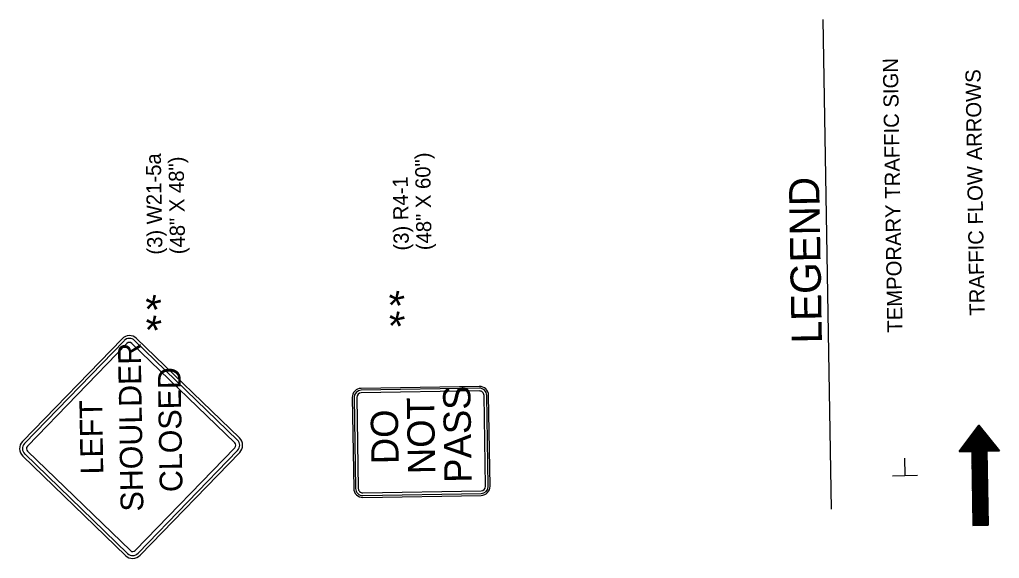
# Model space of a CAD drawing. Extents: x 1676063 to 1678026, y 228339 to 229904.
# Drawn here: x 1677424.3 to 1677812.2, y 228377.9 to 228591.3 of the extents above; entities that cross this region are included whole.
import ezdxf

# ---------------------------------------------------------------- set-up
doc = ezdxf.new("R2010")
doc.units = 0
for name, color, linetype in [('P_TC_Signs_Permanent', 7, 'Continuous'), ('P_TC_Signs_Temporary', 7, 'Continuous'), ('R_Annotation', 7, 'Continuous'), ('R_Draft', 7, 'Continuous'), ('R_MOT', 7, 'Continuous')]:
    doc.layers.add(name, color=color, linetype=linetype)

msp = doc.modelspace()

# ---------------------------------------------------------------- linework, layer by layer
at = {"layer": 'P_TC_Signs_Permanent'}
for p, q in [((1677606.28, 228446), (1677559.49, 228445.22)), ((1677606.29, 228445.28), (1677559.5, 228444.5)), ((1677606.31, 228444.2), (1677559.52, 228443.42)), ((1677555.95, 228441.56), (1677556.54, 228405.57)), ((1677556.67, 228441.58), (1677557.26, 228405.58)), ((1677557.75, 228441.59), (1677558.34, 228405.6)), ((1677608.74, 228406.43), (1677608.14, 228442.43)), ((1677609.82, 228406.45), (1677609.22, 228442.45)), ((1677610.54, 228406.46), (1677609.94, 228442.46)), ((1677560.17, 228403.83), (1677606.97, 228404.6)), ((1677560.19, 228402.75), (1677606.98, 228403.52)), ((1677560.2, 228402.03), (1677607, 228402.81))]:
    msp.add_line(p, q, dxfattribs=at)
for centre, radius, start, end in [((1677559.54, 228441.62), 3.6, 90.9497, 180.9497), ((1677559.54, 228441.62), 2.88, 90.9497, 180.9497), ((1677559.54, 228441.62), 1.8, 90.9497, 180.9497), ((1677606.34, 228442.4), 3.6, 0.9497, 90.9497), ((1677606.34, 228442.4), 2.88, 0.9497, 90.9497), ((1677606.34, 228442.4), 1.8, 0.9497, 90.9497), ((1677560.14, 228405.63), 3.6, 180.9497, 270.9497), ((1677560.14, 228405.63), 2.88, 180.9497, 270.9497), ((1677560.14, 228405.63), 1.8, 180.9497, 270.9497), ((1677606.94, 228406.4), 1.8, 270.9497, 0.9497), ((1677606.94, 228406.4), 2.88, 270.9497, 0.9497), ((1677606.94, 228406.4), 3.6, 270.9497, 0.9497)]:
    msp.add_arc(centre, radius, start, end, dxfattribs=at)
at = {"layer": 'P_TC_Signs_Temporary'}
for p, q in [((1677425.4, 228424.14), (1677464.82, 228464.89)), ((1677426.21, 228423.36), (1677465.63, 228464.11)), ((1677427.34, 228422.26), (1677466.76, 228463.01)), ((1677468.67, 228463.05), (1677509.42, 228423.62)), ((1677469.77, 228464.18), (1677510.52, 228424.76)), ((1677470.55, 228464.99), (1677511.3, 228425.56)), ((1677468.12, 228380.93), (1677427.37, 228420.35)), ((1677509.46, 228421.71), (1677470.03, 228380.96)), ((1677510.59, 228420.62), (1677471.17, 228379.87)), ((1677511.4, 228419.84), (1677471.97, 228379.09)), ((1677466.25, 228378.99), (1677425.49, 228418.41)), ((1677467.03, 228379.8), (1677426.28, 228419.22))]:
    msp.add_line(p, q, dxfattribs=at)
for centre, radius, start, end in [((1677467.73, 228462.08), 4.05, 45.9497, 135.9497), ((1677467.73, 228462.08), 2.93, 45.9497, 135.9497), ((1677467.73, 228462.08), 1.35, 45.9497, 135.9497), ((1677428.31, 228421.32), 4.05, 135.9497, 225.9497), ((1677428.31, 228421.32), 2.93, 135.9497, 225.9497), ((1677508.49, 228422.65), 1.35, 315.9497, 45.9497), ((1677508.49, 228422.65), 2.93, 315.9497, 45.9497), ((1677508.49, 228422.65), 4.05, 315.9497, 45.9497), ((1677428.31, 228421.32), 1.35, 135.9497, 225.9497), ((1677469.06, 228381.9), 1.35, 225.9497, 315.9497), ((1677469.06, 228381.9), 4.05, 225.9497, 315.9497), ((1677469.06, 228381.9), 2.92, 225.9497, 315.9497)]:
    msp.add_arc(centre, radius, start, end, dxfattribs=at)
at = {"layer": 'R_Annotation'}
msp.add_line((1677745.76, 228397.41), (1677742.41, 228591.3), dxfattribs=at)
at = {"layer": 'R_Draft'}
for p, q in [((1677796.23, 228420.15), (1677804.04, 228430.64)), ((1677804.04, 228430.64), (1677812.19, 228420.41)), ((1677796.23, 228420.15), (1677801.22, 228420.23)), ((1677801.22, 228420.23), (1677801.7, 228390.89)), ((1677807.2, 228420.33), (1677812.19, 228420.41)), ((1677807.2, 228420.33), (1677807.69, 228390.99)), ((1677774.83, 228410.83), (1677774.71, 228417.59)), ((1677769.9, 228410.61), (1677779.8, 228410.77)), ((1677801.7, 228390.89), (1677807.69, 228390.99))]:
    msp.add_line(p, q, dxfattribs=at)
at = {"layer": 'R_MOT'}
for p, q in [((1677808.27, 228420.35), (1677801.36, 228427.03)), ((1677808.41, 228420.35), (1677801.42, 228427.12)), ((1677808.55, 228420.35), (1677801.48, 228427.2)), ((1677808.69, 228420.35), (1677801.54, 228427.28)), ((1677808.83, 228420.36), (1677801.6, 228427.36)), ((1677808.98, 228420.36), (1677801.66, 228427.44)), ((1677809.12, 228420.36), (1677801.72, 228427.52)), ((1677809.26, 228420.36), (1677801.78, 228427.6)), ((1677809.4, 228420.37), (1677801.84, 228427.68)), ((1677809.54, 228420.37), (1677801.9, 228427.76)), ((1677809.68, 228420.37), (1677801.96, 228427.84)), ((1677809.82, 228420.37), (1677802.02, 228427.92)), ((1677809.97, 228420.37), (1677802.08, 228428.01)), ((1677810.11, 228420.38), (1677802.14, 228428.09)), ((1677810.25, 228420.38), (1677802.2, 228428.17)), ((1677810.39, 228420.38), (1677802.26, 228428.25)), ((1677810.53, 228420.38), (1677802.32, 228428.33)), ((1677810.67, 228420.39), (1677802.38, 228428.41)), ((1677810.81, 228420.39), (1677802.44, 228428.49)), ((1677810.96, 228420.39), (1677802.5, 228428.57)), ((1677811.1, 228420.39), (1677802.56, 228428.65)), ((1677811.24, 228420.4), (1677802.62, 228428.73)), ((1677811.38, 228420.4), (1677802.68, 228428.81)), ((1677811.52, 228420.4), (1677802.74, 228428.89)), ((1677811.66, 228420.4), (1677802.8, 228428.98)), ((1677811.8, 228420.41), (1677802.86, 228429.06)), ((1677811.95, 228420.41), (1677802.92, 228429.14)), ((1677812.09, 228420.41), (1677802.98, 228429.22)), ((1677812.05, 228420.59), (1677803.04, 228429.3)), ((1677811.56, 228421.19), (1677803.1, 228429.38)), ((1677811.08, 228421.8), (1677803.16, 228429.46)), ((1677810.6, 228422.41), (1677803.22, 228429.54)), ((1677810.11, 228423.02), (1677803.28, 228429.62)), ((1677809.63, 228423.62), (1677803.34, 228429.7)), ((1677809.14, 228424.23), (1677803.4, 228429.78)), ((1677808.66, 228424.84), (1677803.46, 228429.87)), ((1677808.18, 228425.45), (1677803.52, 228429.95)), ((1677807.69, 228426.05), (1677803.58, 228430.03)), ((1677807.21, 228426.66), (1677803.64, 228430.11)), ((1677806.72, 228427.27), (1677803.7, 228430.19)), ((1677806.24, 228427.88), (1677803.76, 228430.27)), ((1677805.75, 228428.48), (1677803.82, 228430.35)), ((1677805.27, 228429.09), (1677803.88, 228430.43)), ((1677804.79, 228429.7), (1677803.94, 228430.51)), ((1677804.3, 228430.31), (1677804, 228430.59)), ((1677807.3, 228414.61), (1677798.47, 228423.15)), ((1677807.29, 228414.75), (1677798.53, 228423.23)), ((1677807.29, 228414.89), (1677798.59, 228423.31)), ((1677807.29, 228415.03), (1677798.65, 228423.39)), ((1677807.29, 228415.18), (1677798.71, 228423.47)), ((1677807.28, 228415.32), (1677798.77, 228423.56)), ((1677807.28, 228415.46), (1677798.83, 228423.64)), ((1677807.28, 228415.6), (1677798.89, 228423.72)), ((1677807.28, 228415.74), (1677798.95, 228423.8)), ((1677807.28, 228415.88), (1677799.01, 228423.88)), ((1677807.27, 228416.02), (1677799.07, 228423.96)), ((1677807.27, 228416.16), (1677799.13, 228424.04)), ((1677807.27, 228416.31), (1677799.19, 228424.12)), ((1677807.27, 228416.45), (1677799.25, 228424.2)), ((1677807.26, 228416.59), (1677799.31, 228424.28)), ((1677807.26, 228416.73), (1677799.37, 228424.36)), ((1677807.26, 228416.87), (1677799.43, 228424.45)), ((1677807.26, 228417.01), (1677799.49, 228424.53)), ((1677807.25, 228417.15), (1677799.55, 228424.61)), ((1677807.25, 228417.3), (1677799.61, 228424.69)), ((1677807.25, 228417.44), (1677799.67, 228424.77)), ((1677807.25, 228417.58), (1677799.73, 228424.85)), ((1677807.24, 228417.72), (1677799.79, 228424.93)), ((1677807.24, 228417.86), (1677799.85, 228425.01)), ((1677807.24, 228418), (1677799.91, 228425.09)), ((1677807.24, 228418.14), (1677799.97, 228425.17)), ((1677807.24, 228418.29), (1677800.03, 228425.25)), ((1677807.23, 228418.43), (1677800.09, 228425.34)), ((1677807.23, 228418.57), (1677800.15, 228425.42)), ((1677807.23, 228418.71), (1677800.21, 228425.5)), ((1677807.23, 228418.85), (1677800.27, 228425.58)), ((1677807.22, 228418.99), (1677800.33, 228425.66)), ((1677807.22, 228419.13), (1677800.39, 228425.74)), ((1677807.22, 228419.28), (1677800.45, 228425.82)), ((1677807.22, 228419.42), (1677800.51, 228425.9)), ((1677807.21, 228419.56), (1677800.57, 228425.98)), ((1677807.21, 228419.7), (1677800.63, 228426.06)), ((1677807.21, 228419.84), (1677800.69, 228426.14)), ((1677807.21, 228419.98), (1677800.75, 228426.23)), ((1677807.2, 228420.12), (1677800.81, 228426.31)), ((1677807.2, 228420.27), (1677800.87, 228426.39)), ((1677807.28, 228420.33), (1677800.93, 228426.47)), ((1677807.42, 228420.33), (1677800.99, 228426.55)), ((1677807.56, 228420.34), (1677801.06, 228426.63)), ((1677807.7, 228420.34), (1677801.12, 228426.71)), ((1677807.84, 228420.34), (1677801.18, 228426.79)), ((1677807.99, 228420.34), (1677801.24, 228426.87)), ((1677808.13, 228420.34), (1677801.3, 228426.95)), ((1677796.39, 228420.15), (1677796.3, 228420.24)), ((1677796.53, 228420.15), (1677796.36, 228420.32)), ((1677796.67, 228420.15), (1677796.42, 228420.4)), ((1677796.82, 228420.16), (1677796.48, 228420.48)), ((1677796.96, 228420.16), (1677796.54, 228420.56)), ((1677797.1, 228420.16), (1677796.6, 228420.64)), ((1677797.24, 228420.16), (1677796.66, 228420.72)), ((1677797.38, 228420.17), (1677796.72, 228420.81)), ((1677797.52, 228420.17), (1677796.78, 228420.89)), ((1677797.66, 228420.17), (1677796.84, 228420.97)), ((1677797.81, 228420.17), (1677796.9, 228421.05)), ((1677797.95, 228420.18), (1677796.96, 228421.13)), ((1677798.09, 228420.18), (1677797.02, 228421.21)), ((1677798.23, 228420.18), (1677797.08, 228421.29)), ((1677798.37, 228420.18), (1677797.14, 228421.37)), ((1677798.51, 228420.19), (1677797.2, 228421.45)), ((1677798.65, 228420.19), (1677797.26, 228421.53)), ((1677798.8, 228420.19), (1677797.32, 228421.61)), ((1677798.94, 228420.19), (1677797.38, 228421.7)), ((1677799.08, 228420.19), (1677797.44, 228421.78)), ((1677799.22, 228420.2), (1677797.5, 228421.86)), ((1677799.36, 228420.2), (1677797.56, 228421.94)), ((1677799.5, 228420.2), (1677797.62, 228422.02)), ((1677799.64, 228420.2), (1677797.68, 228422.1)), ((1677799.78, 228420.21), (1677797.74, 228422.18)), ((1677799.93, 228420.21), (1677797.8, 228422.26)), ((1677800.07, 228420.21), (1677797.86, 228422.34)), ((1677800.21, 228420.21), (1677797.92, 228422.42)), ((1677800.35, 228420.22), (1677797.98, 228422.5)), ((1677800.49, 228420.22), (1677798.05, 228422.58)), ((1677800.63, 228420.22), (1677798.11, 228422.67)), ((1677800.77, 228420.22), (1677798.17, 228422.75)), ((1677800.92, 228420.22), (1677798.23, 228422.83)), ((1677801.06, 228420.23), (1677798.29, 228422.91)), ((1677801.2, 228420.23), (1677798.35, 228422.99)), ((1677807.3, 228414.47), (1677798.41, 228423.07)), ((1677807.3, 228414.33), (1677801.22, 228420.21)), ((1677807.3, 228414.19), (1677801.22, 228420.07)), ((1677807.31, 228414.04), (1677801.22, 228419.93)), ((1677807.31, 228413.9), (1677801.22, 228419.79)), ((1677807.31, 228413.76), (1677801.23, 228419.65)), ((1677807.31, 228413.62), (1677801.23, 228419.5)), ((1677807.31, 228413.48), (1677801.23, 228419.36)), ((1677807.32, 228413.34), (1677801.23, 228419.22)), ((1677807.32, 228413.2), (1677801.24, 228419.08)), ((1677807.32, 228413.05), (1677801.24, 228418.94)), ((1677807.32, 228412.91), (1677801.24, 228418.8)), ((1677807.33, 228412.77), (1677801.24, 228418.66)), ((1677807.33, 228412.63), (1677801.25, 228418.51)), ((1677807.33, 228412.49), (1677801.25, 228418.37)), ((1677807.33, 228412.35), (1677801.25, 228418.23)), ((1677807.34, 228412.21), (1677801.25, 228418.09)), ((1677807.34, 228412.06), (1677801.26, 228417.95)), ((1677807.34, 228411.92), (1677801.26, 228417.81)), ((1677807.34, 228411.78), (1677801.26, 228417.67)), ((1677807.35, 228411.64), (1677801.26, 228417.52)), ((1677807.35, 228411.5), (1677801.26, 228417.38)), ((1677807.35, 228411.36), (1677801.27, 228417.24)), ((1677807.35, 228411.22), (1677801.27, 228417.1)), ((1677807.35, 228411.07), (1677801.27, 228416.96)), ((1677807.36, 228410.93), (1677801.27, 228416.82)), ((1677807.36, 228410.79), (1677801.28, 228416.68)), ((1677807.36, 228410.65), (1677801.28, 228416.53)), ((1677807.36, 228410.51), (1677801.28, 228416.39)), ((1677807.37, 228410.37), (1677801.28, 228416.25)), ((1677807.37, 228410.23), (1677801.29, 228416.11)), ((1677807.37, 228410.08), (1677801.29, 228415.97)), ((1677807.37, 228409.94), (1677801.29, 228415.83)), ((1677807.38, 228409.8), (1677801.29, 228415.69)), ((1677807.38, 228409.66), (1677801.3, 228415.55)), ((1677807.38, 228409.52), (1677801.3, 228415.4)), ((1677807.38, 228409.38), (1677801.3, 228415.26)), ((1677807.39, 228409.24), (1677801.3, 228415.12)), ((1677807.39, 228409.09), (1677801.3, 228414.98)), ((1677807.39, 228408.95), (1677801.31, 228414.84)), ((1677807.39, 228408.81), (1677801.31, 228414.7)), ((1677807.39, 228408.67), (1677801.31, 228414.56)), ((1677807.4, 228408.53), (1677801.31, 228414.41)), ((1677807.4, 228408.39), (1677801.32, 228414.27)), ((1677807.4, 228408.25), (1677801.32, 228414.13)), ((1677807.4, 228408.11), (1677801.32, 228413.99)), ((1677807.41, 228407.96), (1677801.32, 228413.85)), ((1677807.41, 228407.82), (1677801.33, 228413.71)), ((1677807.41, 228407.68), (1677801.33, 228413.57)), ((1677807.41, 228407.54), (1677801.33, 228413.42)), ((1677807.42, 228407.4), (1677801.33, 228413.28)), ((1677807.42, 228407.26), (1677801.34, 228413.14)), ((1677807.42, 228407.12), (1677801.34, 228413)), ((1677807.42, 228406.97), (1677801.34, 228412.86)), ((1677807.43, 228406.83), (1677801.34, 228412.72)), ((1677807.43, 228406.69), (1677801.34, 228412.58)), ((1677807.43, 228406.55), (1677801.35, 228412.43)), ((1677807.43, 228406.41), (1677801.35, 228412.29)), ((1677807.43, 228406.27), (1677801.35, 228412.15)), ((1677807.44, 228406.13), (1677801.35, 228412.01)), ((1677807.44, 228405.98), (1677801.36, 228411.87)), ((1677807.44, 228405.84), (1677801.36, 228411.73)), ((1677807.44, 228405.7), (1677801.36, 228411.59)), ((1677807.45, 228405.56), (1677801.36, 228411.44)), ((1677807.45, 228405.42), (1677801.37, 228411.3)), ((1677807.45, 228405.28), (1677801.37, 228411.16)), ((1677807.45, 228405.14), (1677801.37, 228411.02)), ((1677807.46, 228404.99), (1677801.37, 228410.88)), ((1677807.46, 228404.85), (1677801.37, 228410.74)), ((1677807.46, 228404.71), (1677801.38, 228410.6)), ((1677807.46, 228404.57), (1677801.38, 228410.45)), ((1677807.46, 228404.43), (1677801.38, 228410.31)), ((1677807.47, 228404.29), (1677801.38, 228410.17)), ((1677807.47, 228404.15), (1677801.39, 228410.03)), ((1677807.47, 228404), (1677801.39, 228409.89)), ((1677807.47, 228403.86), (1677801.39, 228409.75)), ((1677807.48, 228403.72), (1677801.39, 228409.61)), ((1677807.48, 228403.58), (1677801.4, 228409.46)), ((1677807.48, 228403.44), (1677801.4, 228409.32)), ((1677807.48, 228403.3), (1677801.4, 228409.18)), ((1677807.49, 228403.16), (1677801.4, 228409.04)), ((1677807.49, 228403.01), (1677801.41, 228408.9)), ((1677807.49, 228402.87), (1677801.41, 228408.76)), ((1677807.49, 228402.73), (1677801.41, 228408.62)), ((1677807.5, 228402.59), (1677801.41, 228408.47)), ((1677807.5, 228402.45), (1677801.41, 228408.33)), ((1677807.5, 228402.31), (1677801.42, 228408.19)), ((1677807.5, 228402.17), (1677801.42, 228408.05)), ((1677807.5, 228402.02), (1677801.42, 228407.91)), ((1677807.51, 228401.88), (1677801.42, 228407.77)), ((1677807.51, 228401.74), (1677801.43, 228407.63)), ((1677807.51, 228401.6), (1677801.43, 228407.49)), ((1677807.51, 228401.46), (1677801.43, 228407.34)), ((1677807.52, 228401.32), (1677801.43, 228407.2)), ((1677807.52, 228401.18), (1677801.44, 228407.06)), ((1677807.52, 228401.03), (1677801.44, 228406.92)), ((1677807.52, 228400.89), (1677801.44, 228406.78)), ((1677807.53, 228400.75), (1677801.44, 228406.64)), ((1677807.53, 228400.61), (1677801.45, 228406.5)), ((1677807.53, 228400.47), (1677801.45, 228406.35)), ((1677807.53, 228400.33), (1677801.45, 228406.21)), ((1677807.54, 228400.19), (1677801.45, 228406.07)), ((1677807.54, 228400.05), (1677801.45, 228405.93)), ((1677807.54, 228399.9), (1677801.46, 228405.79)), ((1677807.54, 228399.76), (1677801.46, 228405.65)), ((1677807.54, 228399.62), (1677801.46, 228405.51)), ((1677807.55, 228399.48), (1677801.46, 228405.36)), ((1677807.55, 228399.34), (1677801.47, 228405.22)), ((1677807.55, 228399.2), (1677801.47, 228405.08)), ((1677807.55, 228399.06), (1677801.47, 228404.94)), ((1677807.56, 228398.91), (1677801.47, 228404.8)), ((1677807.56, 228398.77), (1677801.48, 228404.66)), ((1677807.56, 228398.63), (1677801.48, 228404.52)), ((1677807.56, 228398.49), (1677801.48, 228404.37)), ((1677807.57, 228398.35), (1677801.48, 228404.23)), ((1677807.57, 228398.21), (1677801.49, 228404.09)), ((1677807.57, 228398.07), (1677801.49, 228403.95)), ((1677807.57, 228397.92), (1677801.49, 228403.81)), ((1677807.58, 228397.78), (1677801.49, 228403.67)), ((1677807.58, 228397.64), (1677801.49, 228403.53)), ((1677807.58, 228397.5), (1677801.5, 228403.38)), ((1677807.58, 228397.36), (1677801.5, 228403.24)), ((1677807.58, 228397.22), (1677801.5, 228403.1)), ((1677807.59, 228397.08), (1677801.5, 228402.96)), ((1677807.59, 228396.93), (1677801.51, 228402.82)), ((1677807.59, 228396.79), (1677801.51, 228402.68)), ((1677807.59, 228396.65), (1677801.51, 228402.54)), ((1677807.6, 228396.51), (1677801.51, 228402.39)), ((1677807.6, 228396.37), (1677801.52, 228402.25)), ((1677807.6, 228396.23), (1677801.52, 228402.11)), ((1677807.6, 228396.09), (1677801.52, 228401.97)), ((1677807.61, 228395.94), (1677801.52, 228401.83)), ((1677807.61, 228395.8), (1677801.52, 228401.69)), ((1677807.61, 228395.66), (1677801.53, 228401.55)), ((1677807.61, 228395.52), (1677801.53, 228401.4)), ((1677807.61, 228395.38), (1677801.53, 228401.26)), ((1677807.62, 228395.24), (1677801.53, 228401.12)), ((1677807.62, 228395.1), (1677801.54, 228400.98)), ((1677807.62, 228394.95), (1677801.54, 228400.84)), ((1677807.62, 228394.81), (1677801.54, 228400.7)), ((1677807.63, 228394.67), (1677801.54, 228400.56)), ((1677807.63, 228394.53), (1677801.55, 228400.42)), ((1677807.63, 228394.39), (1677801.55, 228400.27)), ((1677807.63, 228394.25), (1677801.55, 228400.13)), ((1677807.64, 228394.11), (1677801.55, 228399.99)), ((1677807.64, 228393.96), (1677801.56, 228399.85)), ((1677807.64, 228393.82), (1677801.56, 228399.71)), ((1677807.64, 228393.68), (1677801.56, 228399.57)), ((1677807.65, 228393.54), (1677801.56, 228399.43)), ((1677807.65, 228393.4), (1677801.56, 228399.28)), ((1677807.65, 228393.26), (1677801.57, 228399.14)), ((1677807.65, 228393.12), (1677801.57, 228399)), ((1677807.65, 228392.98), (1677801.57, 228398.86)), ((1677807.66, 228392.83), (1677801.57, 228398.72)), ((1677807.66, 228392.69), (1677801.58, 228398.58)), ((1677807.66, 228392.55), (1677801.58, 228398.44)), ((1677807.66, 228392.41), (1677801.58, 228398.29)), ((1677807.67, 228392.27), (1677801.58, 228398.15)), ((1677807.67, 228392.13), (1677801.59, 228398.01)), ((1677807.67, 228391.99), (1677801.59, 228397.87)), ((1677807.67, 228391.84), (1677801.59, 228397.73)), ((1677807.68, 228391.7), (1677801.59, 228397.59)), ((1677807.68, 228391.56), (1677801.6, 228397.45)), ((1677807.68, 228391.42), (1677801.6, 228397.3)), ((1677807.68, 228391.28), (1677801.6, 228397.16)), ((1677807.69, 228391.14), (1677801.6, 228397.02)), ((1677807.69, 228391), (1677801.6, 228396.88)), ((1677807.56, 228390.98), (1677801.61, 228396.74)), ((1677807.41, 228390.98), (1677801.61, 228396.6)), ((1677807.27, 228390.98), (1677801.61, 228396.46)), ((1677807.13, 228390.98), (1677801.61, 228396.31)), ((1677806.99, 228390.97), (1677801.62, 228396.17)), ((1677806.85, 228390.97), (1677801.62, 228396.03)), ((1677806.71, 228390.97), (1677801.62, 228395.89)), ((1677806.57, 228390.97), (1677801.62, 228395.75)), ((1677806.42, 228390.96), (1677801.63, 228395.61)), ((1677806.28, 228390.96), (1677801.63, 228395.47)), ((1677806.14, 228390.96), (1677801.63, 228395.32)), ((1677806, 228390.96), (1677801.63, 228395.18)), ((1677805.86, 228390.96), (1677801.64, 228395.04)), ((1677805.72, 228390.95), (1677801.64, 228394.9)), ((1677805.58, 228390.95), (1677801.64, 228394.76)), ((1677805.43, 228390.95), (1677801.64, 228394.62)), ((1677805.29, 228390.95), (1677801.64, 228394.48)), ((1677805.15, 228390.94), (1677801.65, 228394.33)), ((1677805.01, 228390.94), (1677801.65, 228394.19)), ((1677804.87, 228390.94), (1677801.65, 228394.05)), ((1677804.73, 228390.94), (1677801.65, 228393.91)), ((1677804.59, 228390.93), (1677801.66, 228393.77)), ((1677804.45, 228390.93), (1677801.66, 228393.63)), ((1677804.3, 228390.93), (1677801.66, 228393.49)), ((1677804.16, 228390.93), (1677801.66, 228393.34)), ((1677804.02, 228390.92), (1677801.67, 228393.2)), ((1677803.88, 228390.92), (1677801.67, 228393.06)), ((1677803.74, 228390.92), (1677801.67, 228392.92)), ((1677803.6, 228390.92), (1677801.67, 228392.78)), ((1677803.46, 228390.92), (1677801.67, 228392.64)), ((1677803.31, 228390.91), (1677801.68, 228392.5)), ((1677803.17, 228390.91), (1677801.68, 228392.36)), ((1677803.03, 228390.91), (1677801.68, 228392.21)), ((1677802.89, 228390.91), (1677801.68, 228392.07)), ((1677802.75, 228390.9), (1677801.69, 228391.93)), ((1677802.61, 228390.9), (1677801.69, 228391.79)), ((1677802.47, 228390.9), (1677801.69, 228391.65)), ((1677802.32, 228390.9), (1677801.69, 228391.51)), ((1677802.18, 228390.89), (1677801.7, 228391.37)), ((1677802.04, 228390.89), (1677801.7, 228391.22)), ((1677801.9, 228390.89), (1677801.7, 228391.08)), ((1677801.76, 228390.89), (1677801.7, 228390.94))]:
    msp.add_line(p, q, dxfattribs=at)

# ---------------------------------------------------------------- texts
at = {"layer": 'P_TC_Signs_Permanent'}
for s, rotation, p in [('PASS', 90.9497, (1677603.31, 228407.9)), ('NOT', 90.9094, (1677588.84, 228411.32)), ('DO', 90.9497, (1677574.38, 228415.26))]:
    msp.add_text(s, height=10.8, rotation=rotation, dxfattribs=at).set_placement(p)
at = {"layer": 'P_TC_Signs_Temporary'}
for s, p in [('SHOULDER', (1677473.29, 228396.51)), ('CLOSED', (1677488.79, 228404.19)), ('LEFT', (1677457.41, 228411.19))]:
    msp.add_text(s, height=9, rotation=90.9497, dxfattribs=at).set_placement(p)
at = {"layer": 'R_Annotation'}
for s, height, rotation, p in [('TEMPORARY TRAFFIC SIGN', 6, 90.9885, (1677773.85, 228467.35)), ('TRAFFIC FLOW ARROWS', 6, 90.9885, (1677806.39, 228474.08)), ('(3) W21-5a', 6, 90.9497, (1677480.84, 228498.24)), ('(48" X 48")', 6, 90.9497, (1677489.84, 228498.39)), ('(48" X 60")', 6, 90.9497, (1677587.41, 228500)), ('(3) R4-1', 6, 90.9497, (1677578.41, 228499.85)), ('LEGEND', 12, 90.9885, (1677741.94, 228463.09)), ('*', 12, 135.9497, (1677485.5, 228483.31)), ('*', 12, 135.9497, (1677581.82, 228484.91)), ('*', 12, 135.9497, (1677485.63, 228475.13)), ('*', 12, 135.9497, (1677581.95, 228476.73))]:
    msp.add_text(s, height=height, rotation=rotation, dxfattribs=at).set_placement(p)

doc.saveas('drawing.dxf')
